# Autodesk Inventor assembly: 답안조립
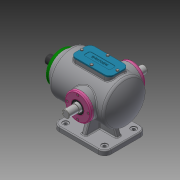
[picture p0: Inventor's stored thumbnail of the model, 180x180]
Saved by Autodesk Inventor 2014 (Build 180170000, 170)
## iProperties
Created: 2021-11
Part Number: 답안조립
Document SubType Name: Assembly
Designer: kb542-02
Author: kb542-02
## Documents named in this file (15)
- C:\Users\kb542-02\Desktop\711106V1007\답안조립.iam
- C:\Users\kb542-02\Desktop\711106V1007\본체.ipt
- C:\Users\kb542-02\Desktop\711106V1007\베어링 6205.ipt
- 베어링 6205.ipt
- C:\Users\kb542-02\Desktop\711106V1007\볼트 M4x0.7.ipt
- C:\Users\kb542-02\Desktop\711106V1007\부시.ipt
- C:\Users\kb542-02\Desktop\711106V1007\상부커버.ipt
- C:\Users\kb542-02\Desktop\711106V1007\슬라이드 커버.ipt
- C:\Users\kb542-02\Desktop\711106V1007\슬라이드.ipt
- C:\Users\kb542-02\Desktop\711106V1007\오일실.ipt
- 오일실.ipt
- C:\Users\kb542-02\Desktop\711106V1007\육각머리볼트 M4.ipt
- C:\Users\kb542-02\Desktop\711106V1007\축 커버.ipt
- C:\Users\kb542-02\Desktop\711106V1007\편심축.ipt
- C:\Users\kb542-02\Desktop\711106V1007\축 커버_MIR.ipt
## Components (12 placed, 1 different names)
1. M4x0.7:1
2. M4x0.7:5
3. M4x0.7:6
4. M4x0.7:7
5. M4x0.7:3
6. M4x0.7:11
7. M4x0.7:12
8. M4x0.7:13
9. M4x0.7:4
10. M4x0.7:14
11. M4x0.7:15
12. M4x0.7:16
